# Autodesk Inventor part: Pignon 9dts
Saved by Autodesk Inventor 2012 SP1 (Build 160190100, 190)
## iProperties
Created: 2014-12
Part Number: Pignon 9dts
Material: Default
Document SubType Name: Modeling
Designer: Bruno
Density: 1 g/cm^3
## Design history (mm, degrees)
node "Pignon 9dts1"
node "Pignon 9dts"
node "Base1"
